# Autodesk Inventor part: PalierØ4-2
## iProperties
Created: 2011-07
Part Number: PalierØ4-2
Document SubType Name: Modeling
Designer: domi
Density: 1 g/cm^3
Author: domi
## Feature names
1. Pallier [Extrusion]
